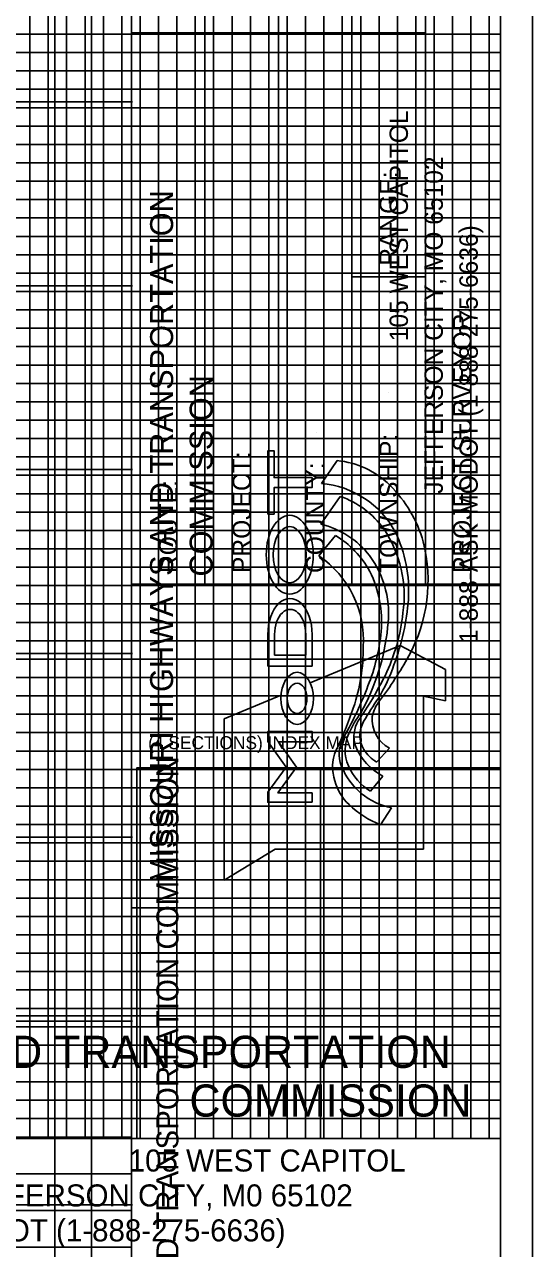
# Model space of a CAD drawing. Extents: x 0 to 31.6, y 0 to 20.8.
# Drawn here: x 28.84 to 31.6, y 3.61 to 10.27 of the extents above; entities that cross this region are included whole.
import ezdxf

# ---------------------------------------------------------------- set-up
doc = ezdxf.new("R2010")
doc.units = 0
for name, color, linetype in [('Border-Border', 7, 'Continuous'), ('Border-Bridge survey map and note', 7, 'Continuous'), ('Border-Bridge survey title block', 7, 'Continuous'), ('Border-Bridge xsection major grid lines', 7, 'Continuous'), ('Border-Bridge xsection minor grid lines', 7, 'Continuous'), ('Border-Full profile major grid lines', 7, 'Continuous'), ('Border-Full xsection major grid lines', 7, 'Continuous'), ('Border-Full xsection minor grid lines', 7, 'Continuous'), ('Border-Plan-profile major grid lines', 7, 'Continuous'), ('Border-Plotting block', 7, 'Continuous'), ('Border-Title block - Final Plans Consultant Manual Seal', 7, 'Continuous'), ('Border-Title block - Final Plans Electronic Seal', 7, 'Continuous'), ('Border-Title block - Location Survey Electronic Seal', 7, 'Continuous'), ('Border-Title block - Standard Plans Electronic Seal', 7, 'Continuous'), ('Border-Xsection shape', 7, 'Continuous')]:
    doc.layers.add(name, color=color, linetype=linetype)

msp = doc.modelspace()

# ---------------------------------------------------------------- linework, layer by layer
at = {"layer": 'Border-Border'}
msp.add_line((31.425, 20.5875), (31.425, 0.2125), dxfattribs=at)
at = {"layer": 'Border-Bridge survey map and note'}
for p, q in [((30.4469, 6.2219), (30.4469, 4.2046)), ((29.4469, 5.2141), (31.4249, 5.2141))]:
    msp.add_line(p, q, dxfattribs=at)
msp.add_lwpolyline([(29.4469, 4.2046), (29.4469, 6.2219), (31.4249, 6.2219)], dxfattribs=at)
at = {"layer": 'Border-Bridge survey title block'}
msp.add_lwpolyline([(26.9414, 0.2125), (26.9414, 4.2047), (31.4249, 4.2047)], dxfattribs=at)
at = {"layer": 'Border-Bridge xsection major grid lines'}
for p, q in [((29.6649, 4.2046), (29.6649, 20.5875)), ((30.6649, 20.5875), (30.6649, 4.2046)), ((0.175, 10.2125), (31.4249, 10.2125)), ((0.175, 9.2125), (31.4249, 9.2125)), ((0.175, 8.2125), (31.4249, 8.2125)), ((0.175, 7.2125), (31.4249, 7.2125)), ((0.175, 6.2125), (31.4249, 6.2125)), ((0.175, 5.2125), (31.4249, 5.2125))]:
    msp.add_line(p, q, dxfattribs=at)
at = {"layer": 'Border-Bridge xsection minor grid lines'}
for p, q in [((28.8649, 20.5875), (28.8649, 4.2046)), ((28.9649, 20.5875), (28.9649, 4.2046)), ((29.0649, 20.5875), (29.0649, 4.2046)), ((29.1649, 20.5875), (29.1649, 4.2046)), ((29.2649, 20.5875), (29.2649, 4.2046)), ((29.3649, 20.5875), (29.3649, 4.2046)), ((29.4649, 20.5875), (29.4649, 4.2046)), ((29.5649, 20.5875), (29.5649, 4.2046)), ((29.7649, 20.5875), (29.7649, 4.2046)), ((29.8649, 20.5875), (29.8649, 4.2046)), ((29.9649, 20.5875), (29.9649, 4.2046)), ((30.0649, 20.5875), (30.0649, 4.2046)), ((30.1649, 20.5875), (30.1649, 4.2046)), ((30.2649, 20.5875), (30.2649, 4.2046)), ((30.3649, 20.5875), (30.3649, 4.2046)), ((30.4649, 20.5875), (30.4649, 4.2046)), ((30.5649, 20.5875), (30.5649, 4.2046)), ((30.7649, 20.5875), (30.7649, 4.2046)), ((30.8649, 20.5875), (30.8649, 4.2046)), ((30.9649, 20.5875), (30.9649, 4.2046)), ((31.0649, 20.5875), (31.0649, 4.2046)), ((31.1649, 20.5875), (31.1649, 4.2046)), ((31.2649, 20.5875), (31.2649, 4.2046)), ((31.3649, 20.5875), (31.3649, 4.2046)), ((31.4249, 10.1125), (0.175, 10.1125)), ((31.4249, 10.0125), (0.175, 10.0125)), ((31.4249, 9.9125), (0.175, 9.9125)), ((31.4249, 9.8125), (0.175, 9.8125)), ((31.4249, 9.7125), (0.175, 9.7125)), ((31.4249, 9.6125), (0.175, 9.6125)), ((31.4249, 9.5125), (0.175, 9.5125)), ((31.4249, 9.4125), (0.175, 9.4125)), ((31.4249, 9.3125), (0.175, 9.3125)), ((31.4249, 9.1125), (0.175, 9.1125)), ((31.4249, 9.0125), (0.175, 9.0125)), ((31.4249, 8.9125), (0.175, 8.9125)), ((31.4249, 8.8125), (0.175, 8.8125)), ((31.4249, 8.7125), (0.175, 8.7125)), ((31.4249, 8.6125), (0.175, 8.6125)), ((31.4249, 8.5125), (0.175, 8.5125)), ((31.4249, 8.4125), (0.175, 8.4125)), ((31.4249, 8.3125), (0.175, 8.3125)), ((31.4249, 8.1125), (0.175, 8.1125)), ((31.4249, 8.0125), (0.175, 8.0125)), ((31.4249, 7.9125), (0.175, 7.9125)), ((31.4249, 7.8125), (0.175, 7.8125)), ((31.4249, 7.7125), (0.175, 7.7125)), ((31.4249, 7.6125), (0.175, 7.6125)), ((31.4249, 7.5125), (0.175, 7.5125)), ((31.4249, 7.4125), (0.175, 7.4125)), ((31.4249, 7.3125), (0.175, 7.3125)), ((31.4249, 7.1125), (0.175, 7.1125)), ((31.4249, 7.0125), (0.175, 7.0125)), ((31.4249, 6.9125), (0.175, 6.9125)), ((31.4249, 6.8125), (0.175, 6.8125)), ((31.4249, 6.7125), (0.175, 6.7125)), ((31.4249, 6.6125), (0.175, 6.6125)), ((31.4249, 6.5125), (0.175, 6.5125)), ((31.4249, 6.4125), (0.175, 6.4125)), ((31.4249, 6.3125), (0.175, 6.3125)), ((31.4249, 6.1125), (0.175, 6.1125)), ((31.4249, 6.0125), (0.175, 6.0125)), ((31.4249, 5.9125), (0.175, 5.9125)), ((31.4249, 5.8125), (0.175, 5.8125)), ((31.4249, 5.7125), (0.175, 5.7125)), ((31.4249, 5.6125), (0.175, 5.6125)), ((31.4249, 5.5125), (0.175, 5.5125)), ((31.4249, 5.4125), (0.175, 5.4125)), ((31.4249, 5.3125), (0.175, 5.3125)), ((31.4249, 5.1125), (0.175, 5.1125)), ((31.4249, 5.0125), (0.175, 5.0125)), ((31.4249, 4.9125), (0.175, 4.9125)), ((31.4249, 4.8125), (0.175, 4.8125)), ((31.4249, 4.7125), (0.175, 4.7125)), ((31.4249, 4.6125), (0.175, 4.6125)), ((31.4249, 4.5125), (0.175, 4.5125)), ((31.4249, 4.4125), (0.175, 4.4125)), ((31.4249, 4.3125), (0.175, 4.3125))]:
    msp.add_line(p, q, dxfattribs=at)
at = {"layer": 'Border-Full profile major grid lines'}
for p, q in [((29.4171, 9.8436), (0.175, 9.8436)), ((29.4171, 8.8436), (0.175, 8.8436)), ((29.4171, 7.8436), (0.175, 7.8436)), ((29.4171, 6.8436), (0.175, 6.8436)), ((29.4171, 5.8436), (0.175, 5.8436)), ((29.4171, 4.8436), (0.175, 4.8436)), ((29.4171, 3.8436), (0.175, 3.8436))]:
    msp.add_line(p, q, dxfattribs=at)
at = {"layer": 'Border-Full xsection major grid lines'}
for p, q in [((0.175, 10.2125), (29.4171, 10.2125)), ((0.175, 9.2125), (29.4171, 9.2125)), ((0.175, 8.2125), (29.4171, 8.2125)), ((0.175, 7.2125), (29.4171, 7.2125)), ((0.175, 6.2125), (29.4171, 6.2125)), ((0.175, 5.2125), (29.4171, 5.2125)), ((0.175, 4.2125), (29.4171, 4.2125)), ((31.4249, 4.2125), (31.4254, 4.2125))]:
    msp.add_line(p, q, dxfattribs=at)
at = {"layer": 'Border-Full xsection minor grid lines'}
for p, q in [((28.9999, 0.2125), (28.9999, 20.5875)), ((29.1999, 0.2125), (29.1999, 20.5875)), ((0.175, 10.0125), (29.4171, 10.0125)), ((0.175, 9.8125), (29.4171, 9.8125)), ((0.175, 9.6125), (29.4171, 9.6125)), ((0.175, 9.4125), (29.4171, 9.4125)), ((0.175, 9.0125), (29.4171, 9.0125)), ((0.175, 8.8125), (29.4171, 8.8125)), ((0.175, 8.6125), (29.4171, 8.6125)), ((0.175, 8.4125), (29.4171, 8.4125)), ((0.175, 8.0125), (29.4171, 8.0125)), ((0.175, 7.8125), (29.4171, 7.8125)), ((0.175, 7.6125), (29.4171, 7.6125)), ((0.175, 7.4125), (29.4171, 7.4125)), ((0.175, 7.0125), (29.4171, 7.0125)), ((0.175, 6.8125), (29.4171, 6.8125)), ((0.175, 6.6125), (29.4171, 6.6125)), ((0.175, 6.4125), (29.4171, 6.4125)), ((0.175, 6.0125), (29.4171, 6.0125)), ((0.175, 5.8125), (29.4171, 5.8125)), ((0.175, 5.6125), (29.4171, 5.6125)), ((0.175, 5.4125), (29.4171, 5.4125)), ((0.175, 5.0125), (29.4171, 5.0125)), ((0.175, 4.8125), (29.4171, 4.8125)), ((0.175, 4.6125), (29.4171, 4.6125)), ((0.175, 4.4125), (29.4171, 4.4125)), ((31.4249, 4.4125), (31.4254, 4.4125)), ((0.175, 4.0125), (29.4171, 4.0125)), ((0.175, 3.8125), (29.4171, 3.8125)), ((0.175, 3.6125), (29.4171, 3.6125))]:
    msp.add_line(p, q, dxfattribs=at)
at = {"layer": 'Border-Plan-profile major grid lines'}
for p, q in [((29.4233, 9.8436), (0.1811, 9.8436)), ((29.4233, 8.8436), (0.1811, 8.8436)), ((29.4233, 7.8436), (0.1811, 7.8436)), ((29.4233, 6.8436), (0.1811, 6.8436)), ((29.4233, 5.8436), (0.1811, 5.8436)), ((29.4233, 4.8436), (0.1811, 4.8436)), ((29.4233, 3.8436), (0.1811, 3.8436))]:
    msp.add_line(p, q, dxfattribs=at)
at = {"layer": 'Border-Plotting block'}
msp.add_lwpolyline([(0, 0), (31.5999, 0), (31.5999, 20.8), (0, 20.8)], close=True, dxfattribs=at)
at = {"layer": 'Border-Title block - Final Plans Consultant Manual Seal'}
for p, q in [((29.4171, 20.5875), (29.4171, 0.2125)), ((30.5365, 7.8922), (30.4519, 7.768)), ((30.5541, 7.6979), (30.4483, 7.5468)), ((30.5272, 7.4859), (30.4378, 7.3747)), ((30.16, 6.9464), (30.16, 6.774)), ((30.1963, 6.8334), (30.1963, 6.9464)), ((30.3662, 6.9464), (30.3662, 6.8334)), ((30.4008, 6.774), (30.4008, 6.9464)), ((30.8803, 6.8869), (30.3903, 6.6831)), ((31.1267, 6.7566), (30.8803, 6.8869)), ((30.3662, 6.8334), (30.1963, 6.8334)), ((30.16, 6.774), (30.4008, 6.774)), ((31.1267, 6.5855), (31.1267, 6.7566)), ((30.2315, 6.617), (29.922, 6.4883)), ((31.0071, 5.7793), (31.0071, 6.6109)), ((31.0071, 6.6109), (31.1267, 6.5855)), ((29.922, 6.4883), (29.922, 5.6099)), ((30.7517, 6.2525), (30.821, 6.3285)), ((30.7188, 6.0943), (30.7857, 6.1748)), ((30.7729, 5.9114), (30.8329, 6.0039)), ((29.922, 5.6099), (30.2004, 5.7793)), ((30.2004, 5.7793), (31.0071, 5.7793)), ((29.4171, 5.4599), (31.425, 5.4599))]:
    msp.add_line(p, q, dxfattribs=at)
for points in [[(30.1599, 7.6015), (30.1599, 7.9459), (30.1934, 7.9459), (30.1934, 7.8005), (30.4008, 7.8005), (30.4008, 7.7459), (30.1934, 7.7459), (30.1934, 7.6015)], [(30.4008, 6.0337), (30.1592, 6.0337), (30.1592, 6.0882), (30.2588, 6.2251), (30.16, 6.3638), (30.16, 6.4193), (30.4008, 6.4193), (30.4008, 6.3619), (30.2185, 6.3619), (30.3164, 6.2251), (30.2147, 6.0844), (30.4008, 6.0844)]]:
    msp.add_lwpolyline(points, close=True, dxfattribs=at)
for centre, radius, start, end in [((30.4952, 7.4285), 0.4656, 45.16931, 84.90202), ((30.4076, 7.2631), 0.5069, 28.57249, 84.98895), ((30.3292, 7.2587), 0.7029, 15.82215, 45.3322), ((30.3947, 7.2387), 0.486, 35.48059, 70.84743), ((30.3361, 7.0832), 0.477, 37.82053, 76.39644), ((30.2447, 7.0264), 0.5393, 29.26655, 58.41911), ((30.2462, 7.1558), 0.6553, 351.92721, 33.85401), ((30.1918, 7.186), 0.7342, 356.25263, 25.80365), ((30.1706, 7.2409), 0.8608, 331.45894, 14.08516), ((30.1256, 6.9166), 0.5543, 55.72742, 55.72758), ((30.1256, 6.9166), 0.5543, 356.10332, 55.7272), ((30.2854, 7.0598), 0.5315, 351.87184, 36.46402), ((30.1519, 7.0155), 0.6267, 355.20478, 25.98369), ((29.6592, 7.2299), 1.2685, 339.27778, 355.84654), ((29.8531, 7.1765), 1.048, 334.30971, 353.82369), ((29.6238, 7.1031), 1.1937, 330.80189, 354.30584), ((29.6939, 7.068), 1.0875, 338.33661, 354.46616), ((29.6632, 6.8729), 1.0155, 341.46898, 0.34157), ((29.0087, 7.8983), 2.1957, 323.25469, 330.87553), ((30.017, 7.0594), 0.8742, 328.33342, 341.42803), ((28.6965, 7.4396), 2.1518, 330.82713, 338.94553), ((28.929, 7.6684), 2.0944, 325.33774, 333.14131), ((33.478, 4.796), 3.2616, 146.40943, 149.03928), ((28.5928, 7.2437), 2.1483, 334.37273, 341.16645), ((30.9123, 6.4645), 0.1877, 140.18798, 168.85058), ((31.1325, 6.1801), 0.5778, 143.87617, 156.87144), ((30.7955, 6.3922), 0.167, 149.40426, 197.76384), ((30.8136, 6.3982), 0.1526, 150.25518, 210.64132), ((30.9045, 6.4846), 0.177, 174.75269, 241.86614), ((30.7795, 6.3173), 0.1996, 153.27349, 205.14999), ((30.7203, 6.2966), 0.1729, 147.01991, 203.02392), ((30.9419, 6.465), 0.3295, 202.06293, 241.72012), ((30.7493, 6.2245), 0.2373, 157.70916, 198.17281), ((30.8522, 6.4245), 0.1993, 211.49535, 239.68972), ((30.9032, 6.3653), 0.3681, 201.72885, 258.99607), ((30.8578, 6.3362), 0.279, 201.81038, 240.11136), ((30.7878, 6.2214), 0.2733, 195.0361, 226.99124), ((30.9511, 6.3774), 0.4989, 225.49883, 249.07866)]:
    msp.add_arc(centre, radius, start, end, dxfattribs=at)
for centre, major_axis, ratio in [((30.2788, 7.3805), (0, 0.2144), 0.595517), ((30.2788, 7.3804), (0, -0.153), 0.589579), ((30.3191, 6.5992), (0, 0.1416), 0.623747), ((30.3191, 6.5992), (0, 0.0823), 0.65252)]:
    msp.add_ellipse(centre, major_axis=major_axis, ratio=ratio, dxfattribs=at)
for centre, major_axis, ratio in [((30.2803, 6.9463), (0, -0.1961), 0.614143), ((30.2812, 6.9463), (0, -0.1368), 0.62091)]:
    msp.add_ellipse(centre, major_axis=major_axis, ratio=ratio, start_param=1.570796, end_param=4.712389, dxfattribs=at)
at = {"layer": 'Border-Title block - Final Plans Electronic Seal'}
for p, q in [((29.4171, 20.5875), (29.4171, 0.2125)), ((30.5365, 7.8922), (30.4519, 7.768)), ((30.5541, 7.6979), (30.4483, 7.5468)), ((30.5272, 7.4859), (30.4378, 7.3747)), ((30.16, 6.9464), (30.16, 6.774)), ((30.1963, 6.8334), (30.1963, 6.9464)), ((30.3662, 6.9464), (30.3662, 6.8334)), ((30.4008, 6.774), (30.4008, 6.9464)), ((30.8803, 6.8869), (30.3903, 6.6831)), ((31.1267, 6.7566), (30.8803, 6.8869)), ((30.3662, 6.8334), (30.1963, 6.8334)), ((30.16, 6.774), (30.4008, 6.774)), ((31.1267, 6.5855), (31.1267, 6.7566)), ((30.2315, 6.617), (29.922, 6.4883)), ((31.0071, 5.7793), (31.0071, 6.6109)), ((31.0071, 6.6109), (31.1267, 6.5855)), ((29.922, 6.4883), (29.922, 5.6099)), ((30.7517, 6.2525), (30.821, 6.3285)), ((30.7188, 6.0943), (30.7857, 6.1748)), ((30.7729, 5.9114), (30.8329, 6.0039)), ((29.922, 5.6099), (30.2004, 5.7793)), ((30.2004, 5.7793), (31.0071, 5.7793)), ((29.4171, 5.4599), (31.425, 5.4599))]:
    msp.add_line(p, q, dxfattribs=at)
for points in [[(30.1599, 7.6015), (30.1599, 7.9459), (30.1934, 7.9459), (30.1934, 7.8005), (30.4008, 7.8005), (30.4008, 7.7459), (30.1934, 7.7459), (30.1934, 7.6015)], [(30.4008, 6.0337), (30.1592, 6.0337), (30.1592, 6.0882), (30.2588, 6.2251), (30.16, 6.3638), (30.16, 6.4193), (30.4008, 6.4193), (30.4008, 6.3619), (30.2185, 6.3619), (30.3164, 6.2251), (30.2147, 6.0844), (30.4008, 6.0844)]]:
    msp.add_lwpolyline(points, close=True, dxfattribs=at)
for centre, radius, start, end in [((30.4952, 7.4285), 0.4656, 45.16931, 84.90202), ((30.4076, 7.2631), 0.5069, 28.57249, 84.98895), ((30.3292, 7.2587), 0.7029, 15.82215, 45.3322), ((30.3947, 7.2387), 0.486, 35.48059, 70.84743), ((30.3361, 7.0832), 0.477, 37.82053, 76.39644), ((30.2447, 7.0264), 0.5393, 29.26655, 58.41911), ((30.2462, 7.1558), 0.6553, 351.92721, 33.85401), ((30.1918, 7.186), 0.7342, 356.25263, 25.80365), ((30.1706, 7.2409), 0.8608, 331.45894, 14.08516), ((30.1256, 6.9166), 0.5543, 55.72742, 55.72758), ((30.1256, 6.9166), 0.5543, 356.10332, 55.7272), ((30.2854, 7.0598), 0.5315, 351.87184, 36.46402), ((30.1519, 7.0155), 0.6267, 355.20478, 25.98369), ((29.6592, 7.2299), 1.2685, 339.27778, 355.84654), ((29.8531, 7.1765), 1.048, 334.30971, 353.82369), ((29.6238, 7.1031), 1.1937, 330.80189, 354.30584), ((29.6939, 7.068), 1.0875, 338.33661, 354.46616), ((29.6632, 6.8729), 1.0155, 341.46898, 0.34157), ((29.0087, 7.8983), 2.1957, 323.25469, 330.87553), ((30.017, 7.0594), 0.8742, 328.33342, 341.42803), ((28.6965, 7.4396), 2.1518, 330.82713, 338.94553), ((28.929, 7.6684), 2.0944, 325.33774, 333.14131), ((33.478, 4.796), 3.2616, 146.40943, 149.03928), ((28.5928, 7.2437), 2.1483, 334.37273, 341.16645), ((30.9123, 6.4645), 0.1877, 140.18798, 168.85058), ((31.1325, 6.1801), 0.5778, 143.87617, 156.87144), ((30.7955, 6.3922), 0.167, 149.40426, 197.76384), ((30.8136, 6.3982), 0.1526, 150.25518, 210.64132), ((30.9045, 6.4846), 0.177, 174.75269, 241.86614), ((30.7795, 6.3173), 0.1996, 153.27349, 205.14999), ((30.7203, 6.2966), 0.1729, 147.01991, 203.02392), ((30.9419, 6.465), 0.3295, 202.06293, 241.72012), ((30.7493, 6.2245), 0.2373, 157.70916, 198.17281), ((30.8522, 6.4245), 0.1993, 211.49535, 239.68972), ((30.9032, 6.3653), 0.3681, 201.72885, 258.99607), ((30.8578, 6.3362), 0.279, 201.81038, 240.11136), ((30.7878, 6.2214), 0.2733, 195.0361, 226.99124), ((30.9511, 6.3774), 0.4989, 225.49883, 249.07866)]:
    msp.add_arc(centre, radius, start, end, dxfattribs=at)
for centre, major_axis, ratio in [((30.2788, 7.3805), (0, 0.2144), 0.595517), ((30.2788, 7.3804), (0, -0.153), 0.589579), ((30.3191, 6.5992), (0, 0.1416), 0.623747), ((30.3191, 6.5992), (0, 0.0823), 0.65252)]:
    msp.add_ellipse(centre, major_axis=major_axis, ratio=ratio, dxfattribs=at)
for centre, major_axis, ratio in [((30.2803, 6.9463), (0, -0.1961), 0.614143), ((30.2812, 6.9463), (0, -0.1368), 0.62091)]:
    msp.add_ellipse(centre, major_axis=major_axis, ratio=ratio, start_param=1.570796, end_param=4.712389, dxfattribs=at)
at = {"layer": 'Border-Title block - Location Survey Electronic Seal'}
for p, q in [((29.4171, 20.5875), (29.4171, 0.2125)), ((29.8171, 13.2202), (29.8171, 7.2202)), ((30.2171, 13.2202), (30.2171, 7.2202)), ((30.6171, 13.2202), (30.6171, 7.2202)), ((31.0171, 13.2202), (31.0171, 7.2202)), ((29.4171, 10.2202), (31.0171, 10.2202)), ((30.8117, 9.6142), (30.8117, 9.6142)), ((31.2171, 9.0806), (31.2171, 9.0806)), ((30.6171, 8.8921), (31.0171, 8.8921)), ((30.8171, 8.2648), (30.8171, 8.2648)), ((30.8171, 8.2648), (30.8171, 8.2648)), ((30.0171, 8.115), (30.0171, 8.115)), ((30.4229, 8.0446), (30.4229, 8.0446)), ((29.6171, 7.9411), (29.6171, 7.9411)), ((29.4171, 7.2202), (31.425, 7.2202))]:
    msp.add_line(p, q, dxfattribs=at)
at = {"layer": 'Border-Title block - Standard Plans Electronic Seal'}
msp.add_line((23.4249, 4.8718), (31.425, 4.8718), dxfattribs=at)
at = {"layer": 'Border-Xsection shape'}
msp.add_lwpolyline([(29.4171, 0.2125), (0.175, 0.2125), (0.175, 20.5875), (29.4171, 20.5875)], close=True, dxfattribs=at)

# ---------------------------------------------------------------- texts
at = {"layer": 'Border-Bridge survey map and note'}
msp.add_text('(4 SECTIONS) INDEX MAP', height=0.070563, dxfattribs=at).set_placement((29.5084, 6.3227))
at = {"layer": 'Border-Title block - Final Plans Consultant Manual Seal'}
for s, height, p in [('105 WEST CAPITOL', 0.1, (30.922, 8.542)), ('JEFFERSON CITY, MO 65102', 0.1, (31.112, 7.712)), ('MISSOURI HIGHWAYS AND TRANSPORTATION', 0.125, (29.6442, 5.5933)), ('1-888-ASK-MODOT (1-888-275-6636)', 0.1, (31.302, 6.8991)), ('COMMISSION', 0.125, (29.8592, 7.2617))]:
    msp.add_text(s, height=height, rotation=90, dxfattribs=at).set_placement(p)
at = {"layer": 'Border-Title block - Final Plans Electronic Seal'}
for s, height, p in [('105 WEST CAPITOL', 0.1, (30.922, 8.542)), ('JEFFERSON CITY, MO 65102', 0.1, (31.112, 7.712)), ('MISSOURI HIGHWAYS AND TRANSPORTATION', 0.125, (29.6442, 5.5933)), ('1-888-ASK-MODOT (1-888-275-6636)', 0.1, (31.302, 6.8991)), ('COMMISSION', 0.125, (29.8592, 7.2617))]:
    msp.add_text(s, height=height, rotation=90, dxfattribs=at).set_placement(p)
at = {"layer": 'Border-Title block - Location Survey Electronic Seal'}
for s, height, p in [('RANGE:', 0.1, (30.8671, 8.9528)), ('PROJECT SURVEYOR:', 0.1, (31.2671, 7.281)), ('TOWNSHIP:', 0.1, (30.8671, 7.281)), ('PROJECT:', 0.1, (30.0671, 7.281)), ('COUNTY:', 0.1, (30.4671, 7.281)), ('ROUTE:', 0.1, (29.6671, 7.281)), ('SURVEY FOR: MISSOURI HIGHWAYS AND TRANSPORTATION COMMISSION', 0.12, (29.6734, 0.4356))]:
    msp.add_text(s, height=height, rotation=90, dxfattribs=at).set_placement(p)
at = {"layer": 'Border-Title block - Standard Plans Electronic Seal'}
for s, height, p in [('MISSOURI HIGHWAYS AND TRANSPORTATION', 0.175, (25.8764, 4.5883)), ('COMMISSION', 0.175, (29.733, 4.3233)), ('105 WEST CAPITOL', 0.12, (29.4026, 4.0246)), ('JEFFERSON CITY, M0 65102', 0.12, (28.4547, 3.8346)), ('1-888-ASK-MODOT (1-888-275-6636)', 0.12, (27.5272, 3.6446))]:
    msp.add_text(s, height=height, dxfattribs=at).set_placement(p)

doc.saveas('drawing.dxf')
